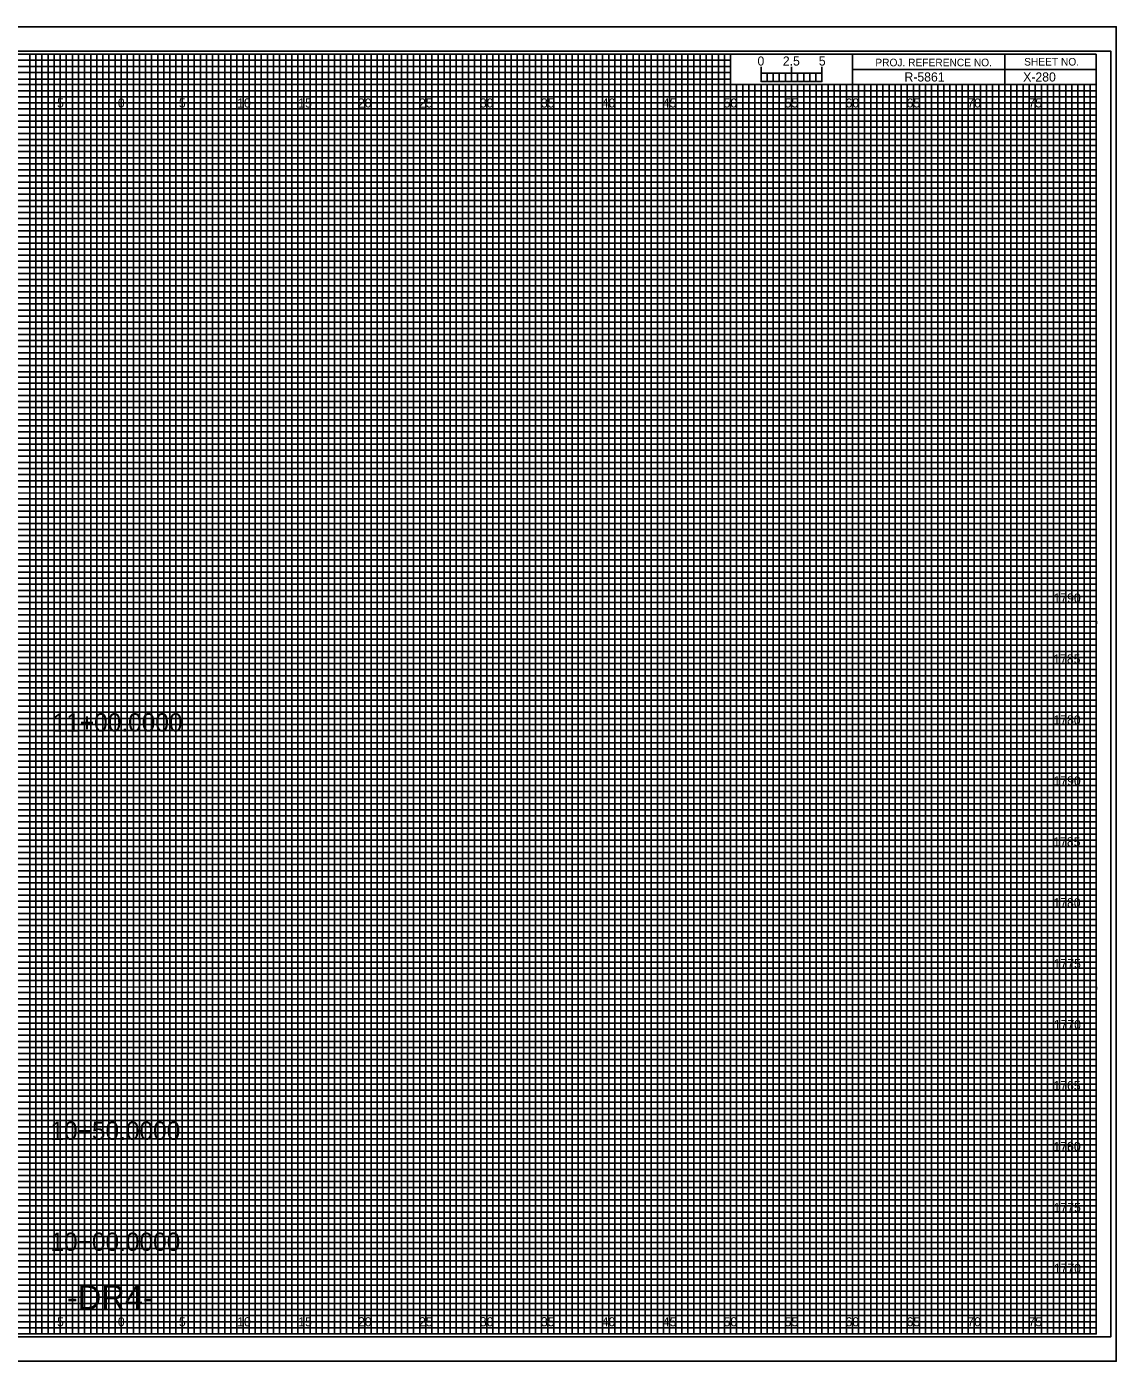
# Model space of a CAD drawing. Extents: x -7 to 162, y -2 to 107.
# Drawn here: x 72.2 to 161.7, y -2.3 to 107.3 of the extents above; entities that cross this region are included whole.
import ezdxf

# ---------------------------------------------------------------- set-up
doc = ezdxf.new("R2010")
doc.units = 0
for name, color, linetype in [('Prop XS Alignment Label', 7, 'Continuous'), ('Prop XS Bar Scale Labels', 7, 'Continuous'), ('Prop XS Elevation Labels', 7, 'Continuous'), ('Prop XS Offset Labels', 7, 'Continuous'), ('Prop XS Project Number', 7, 'Continuous'), ('Prop XS Sheet Number', 7, 'Continuous'), ('Prop XS Station Labels', 7, 'Continuous'), ('Sheet Cross Section CELL', 7, 'Continuous'), ('Sheet Cross Section Grid Major CELL', 7, 'Continuous'), ('Sheet Cross Section Grid Middle CELL', 7, 'Continuous'), ('Sheet Cross Section Grid Minor 1 CELL', 7, 'Continuous'), ('Sheet Cross Section Grid Minor 2 CELL', 7, 'Continuous'), ('Sheet Cross Section Scale CELL', 7, 'Continuous'), ('Sheet Cutting Line CELL', 7, 'Continuous'), ('Sheet DOT Grid CELL', 7, 'Continuous'), ('Sheet Plot Border Inside CELL', 7, 'Continuous'), ('Sheet Plot Border Outside CELL', 7, 'Continuous')]:
    doc.layers.add(name, color=color, linetype=linetype)

msp = doc.modelspace()

# ---------------------------------------------------------------- linework, layer by layer
at = {"layer": 'Sheet Cross Section CELL'}
for p, q in [((152.5, 105), (152.5, 102.5)), ((152.5, 102.5), (152.5, 105)), ((160, 103.75), (140, 103.75)), ((140, 103.75), (140, 102.5)), ((140, 102.5), (160, 102.5))]:
    msp.add_line(p, q, dxfattribs=at)
for points in [[(160, 105), (0, 105), (0, 0), (160, 0)], [(140, 105), (130, 105), (130, 102.52), (140, 102.52)], [(160, 105), (140, 105), (140, 102.5), (160, 102.5)]]:
    msp.add_lwpolyline(points, close=True, dxfattribs=at)
at = {"layer": 'Sheet Cross Section Grid Major CELL'}
for p, q in [((75, 105), (70, 105)), ((75, 0), (75, 105)), ((85, 105), (80, 105)), ((80, 105), (80, 0)), ((85, 0), (85, 105)), ((95, 105), (90, 105)), ((90, 105), (90, 0)), ((95, 0), (95, 105)), ((105, 105), (100, 105)), ((100, 105), (100, 0)), ((105, 0), (105, 105)), ((115, 105), (110, 105)), ((110, 105), (110, 0)), ((115, 0), (115, 105)), ((125, 105), (120, 105)), ((120, 105), (120, 0)), ((125, 0), (125, 105)), ((130, 105), (130, 0)), ((135, 0), (135, 102.5)), ((145, 102.5), (140, 102.5)), ((140, 102.5), (140, 0)), ((145, 0), (145, 102.5)), ((155, 102.5), (150, 102.5)), ((150, 102.5), (150, 0)), ((155, 0), (155, 102.5)), ((80, 0), (75, 0)), ((90, 0), (85, 0)), ((100, 0), (95, 0)), ((110, 0), (105, 0)), ((120, 0), (115, 0)), ((130, 0), (125, 0)), ((140, 0), (135, 0)), ((150, 0), (145, 0)), ((160, 0), (155, 0)), ((160, 0), (160, 0))]:
    msp.add_line(p, q, dxfattribs=at)
for points in [[(0, 100), (160, 100), (160, 95), (0, 95)], [(0, 90), (160, 90), (160, 85), (0, 85)], [(0, 80), (160, 80), (160, 75), (0, 75)], [(0, 70), (160, 70), (160, 65), (0, 65)], [(0, 60), (160, 60), (160, 55), (0, 55)], [(0, 50), (160, 50), (160, 45), (0, 45)], [(0, 40), (160, 40), (160, 35), (0, 35)], [(0, 30), (160, 30), (160, 25), (0, 25)], [(0, 20), (160, 20), (160, 15), (0, 15)], [(0, 10), (160, 10), (160, 5), (0, 5)]]:
    msp.add_lwpolyline(points, dxfattribs=at)
at = {"layer": 'Sheet Cross Section Grid Middle CELL'}
for points in [[(67.5, 105), (72.5, 105), (72.5, 0), (77.5, 0), (77.5, 105), (82.5, 105), (82.5, 0), (87.5, 0), (87.5, 105), (92.5, 105), (92.5, 0), (97.5, 0), (97.5, 105), (102.5, 105), (102.5, 0), (107.5, 0), (107.5, 105), (112.5, 105), (112.5, 0), (117.5, 0), (117.5, 105), (122.5, 105), (122.5, 0), (127.5, 0), (127.5, 105), (129.97, 105), (130, 105), (130, 102.5), (132.5, 102.5), (132.5, 0), (137.5, 0), (137.5, 102.5), (142.5, 102.5), (142.5, 0), (147.5, 0), (147.5, 102.5), (152.5, 102.5), (152.5, 0), (157.5, 0), (157.5, 102.5)], [(0, 102.5), (137.5, 102.5)], [(0, 92.5), (160, 92.5), (160, 97.5), (0, 97.5)], [(0, 82.5), (160, 82.5), (160, 87.5), (0, 87.5)], [(0, 72.5), (160, 72.5), (160, 77.5), (0, 77.5)], [(0, 62.5), (160, 62.5), (160, 67.5), (0, 67.5)], [(0, 52.5), (160, 52.5), (160, 57.5), (0, 57.5)], [(0, 42.5), (160, 42.5), (160, 47.5), (0, 47.5)], [(0, 32.5), (160, 32.5), (160, 37.5), (0, 37.5)], [(0, 22.5), (160, 22.5), (160, 27.5), (0, 27.5)], [(0, 12.5), (160, 12.5), (160, 17.5), (0, 17.5)], [(0, 2.5), (160, 2.5), (160, 7.5), (0, 7.5)]]:
    msp.add_lwpolyline(points, dxfattribs=at)
at = {"layer": 'Sheet Cross Section Grid Minor 1 CELL'}
for p, q in [((0, 104.5), (130, 104.5)), ((130, 104.5), (130, 103.99)), ((130, 103.99), (0, 103.99)), ((0, 103.5), (130, 103.5)), ((130, 102.95), (0, 102.95)), ((130, 103.5), (130, 102.95)), ((0, 102), (160, 102))]:
    msp.add_line(p, q, dxfattribs=at)
for points in [[(0, 101.5), (135, 101.5), (160, 101.5), (160, 101), (0, 101)], [(0, 100.5), (160, 100.5), (160, 99.5), (0, 99.5)], [(0, 99), (160, 99), (160, 98.5), (0, 98.49)], [(0, 98), (160, 98), (160, 97), (0, 97)], [(0, 96.5), (160, 96.5), (160, 96), (0, 96)], [(0, 95.5), (160, 95.5), (160, 94.5), (0, 94.5)], [(0, 94), (160, 94), (160, 93.5), (0, 93.5)], [(0, 93), (160, 93), (160, 92), (0, 92)], [(0, 91.5), (160, 91.5), (160, 91), (0, 91)], [(0, 90.5), (160, 90.5), (160, 89.5), (0, 89.5)], [(0, 89), (160, 89), (160, 88.5), (0, 88.5)], [(0, 88), (160, 88), (160, 86.98), (160, 86.5), (160, 86), (0, 86)], [(0, 87), (160, 87), (160, 86.5), (0, 86.5)], [(0, 85.5), (160, 85.5), (160, 84.5), (0, 84.52)], [(0, 84.52), (160, 84.5), (160, 84), (0, 84)], [(0, 83.5), (160, 83.5), (160, 83), (0, 83)], [(0, 82), (160, 82), (160, 81.5), (0, 81.5)], [(0, 81), (160, 81), (160, 80.5), (0, 80.5)], [(-0.04, 79.45), (160, 79.45), (160, 78.94), (-0.04, 78.94)], [(0, 78.5), (160, 78.5), (160, 78), (0, 78)], [(0, 77), (160, 77), (160, 76.5), (0, 76.5)], [(0, 76), (160, 76), (160, 75.5), (0, 75.5)], [(0, 74.5), (160, 74.5), (160, 74), (0, 74)], [(0, 73.5), (160, 73.5), (160, 73), (0, 73)], [(0, 72), (160, 72), (160, 71.5), (0, 71.5)], [(0, 71), (160, 71), (160, 70.5), (0, 70.5)], [(0, 69.5), (160, 69.5), (160, 68.99), (0, 69)], [(0, 68.5), (160, 68.5), (160, 68), (0, 68)], [(0, 67), (160, 67), (160, 66.5), (0, 66.5)], [(0, 66), (160, 66), (160, 65.5), (0, 65.5)], [(0, 64.5), (160, 64.5), (160, 64), (0, 64)], [(0, 63.5), (160, 63.5), (160, 63), (0, 63)], [(0, 62), (160, 62), (160, 61.5), (0, 61.5)], [(0, 61), (160, 61), (160, 60.5), (0, 60.5)], [(0, 59.5), (160, 59.5), (160, 59), (0, 59)], [(0, 58.5), (160.03, 58.45), (160, 58), (0, 58)], [(0, 57), (160, 57), (160, 56.5), (0, 56.5)], [(0, 56), (160, 56), (160, 55.5), (0, 55.5)], [(0, 54.5), (160, 54.5), (160, 54), (0, 54)], [(0, 53.5), (160, 53.5), (160, 53), (0, 53)], [(0, 52), (160, 52), (160, 51.5), (0, 51.5)], [(0, 51), (160, 51), (160, 50.5), (0, 50.5)], [(0, 49.5), (160, 49.5), (160, 49), (0, 49)], [(0, 48.5), (160, 48.5), (160, 48), (0, 48)], [(0, 47), (160, 47), (160, 46.5), (0, 46.5)], [(0, 46), (160, 46), (160, 45.5), (0, 45.5)], [(0, 44.5), (160, 44.5), (160, 44), (0, 44)], [(0, 43.5), (160, 43.5), (160, 43), (0, 43)], [(0, 42), (160, 42), (160, 41.5), (0, 41.5)], [(0, 41), (160, 41), (160, 40.5), (0, 40.5)], [(0, 39.5), (160, 39.5), (160, 38.99), (0, 39)], [(0, 38.5), (160, 38.5), (160, 38), (0, 38)], [(0, 37), (160, 37), (160, 36.5), (0, 36.5)], [(0, 36), (160, 36), (160, 35.5), (0, 35.5)], [(0, 34.5), (160, 34.5), (160, 34), (0, 34)], [(0, 33.5), (160, 33.5), (160, 33), (0, 33)], [(0, 32), (160, 32), (160, 31.5), (0, 31.5)], [(0, 31), (160, 31), (160, 30.5), (0, 30.5)], [(0, 29.5), (160, 29.5), (160, 29), (0, 29)], [(0, 28.5), (160.03, 28.46), (160, 28), (0, 28)], [(0, 27), (160, 27), (160, 26.5), (0, 26.5)], [(0, 26), (160, 26), (160, 25.5), (0, 25.5)], [(0, 24.5), (160, 24.5), (160, 24), (0, 24)], [(0, 23.5), (160, 23.5), (160, 23), (0, 23)], [(0, 22), (160, 22), (160, 21.5), (0, 21.5)], [(0, 21), (160, 21), (160, 20.5), (0, 20.5)], [(0, 19.5), (160, 19.5), (160, 19), (0, 19)], [(0, 18.5), (160, 18.5), (160, 18), (0, 18)], [(0, 17), (160, 17), (160, 16.5), (0, 16.5)], [(0, 16), (160, 16), (160, 15.5), (0, 15.5)], [(0, 14.5), (160, 14.5), (160, 14), (0, 14)], [(0, 13.5), (160, 13.5), (160, 13), (0, 13)], [(0, 12), (160, 12), (160, 11.5), (0, 11.5)], [(0, 11), (160, 11), (160, 10.5), (0, 10.5)], [(0, 9.5), (160, 9.5), (160, 9), (0, 9)], [(0, 8.5), (160, 8.5), (160, 8), (0, 8)], [(0, 7), (160, 7), (160, 6.5), (0, 6.5)], [(0, 6), (160, 6), (160, 5.5), (0, 5.5)], [(0, 4.5), (160, 4.5), (160, 4), (0, 4)], [(0, 3.5), (160, 3.5), (160, 3), (0, 3)], [(0, 2), (160, 2), (160, 1.5), (0, 1.5)], [(0, 1), (160, 1), (160, 0.5), (0, 0.5)]]:
    msp.add_lwpolyline(points, dxfattribs=at)
at = {"layer": 'Sheet Cross Section Grid Minor 2 CELL'}
for p, q in [((133.5, 102.5), (133, 102.5)), ((133, 102.5), (133, 0)), ((133.5, 0), (133.5, 102.5)), ((134.5, 102.5), (134, 102.5)), ((134, 102.5), (134, 0)), ((134.5, 0), (134.5, 102.5)), ((133, 0), (132.5, 0)), ((134, 0), (133.5, 0))]:
    msp.add_line(p, q, dxfattribs=at)
for points in [[(72.5, 0), (73, 0), (73, 105), (73.5, 105), (73.5, 0)], [(73.5, 0), (74, 0), (74, 105), (74.5, 105), (74.5, 0)], [(75, 0), (75.5, 0), (75.5, 105), (76, 105), (76, 0)], [(76, 0), (76.5, 0), (76.5, 105), (77, 105), (77, 0)], [(77.5, 0), (78, 0), (78, 105), (78.5, 105), (78.5, 0)], [(78.5, 0), (79, 0), (79, 105), (79.5, 105), (79.5, 0)], [(80, 0), (80.5, 0), (80.5, 105), (81, 105), (81, 0)], [(81, 0), (81.5, 0), (81.5, 105), (82, 105), (82, 0)], [(82.5, 0), (83, 0), (83, 105), (83.5, 105), (83.5, 0)], [(83.5, 0), (84, 0), (84, 105), (84.5, 105), (84.5, 0)], [(85, 0), (85.5, 0), (85.5, 105), (86, 105), (86, 0)], [(86, 0), (86.5, 0), (86.5, 105), (87, 105), (87, 0)], [(87.5, 0), (88, 0), (88, 105), (88.5, 105), (88.5, 0)], [(88.5, 0), (89, 0), (89, 105), (89.5, 105), (89.5, 0)], [(90, 0), (90.5, 0), (90.5, 105), (91, 105), (91, 0)], [(91, 0), (91.5, 0), (91.5, 105), (92, 105), (92, 0)], [(92.5, 0), (93, 0), (93, 105), (93.5, 105), (93.5, 0)], [(93.5, 0), (94, 0), (94, 105), (94.5, 105), (94.5, 0)], [(95, 0), (95.5, 0), (95.5, 105), (96, 105), (96, 0)], [(96, 0), (96.5, 0), (96.5, 105), (97, 105), (97, 0)], [(97.5, 0), (98, 0), (98, 105), (98.5, 105), (98.5, 0)], [(98.5, 0), (99, 0), (99, 105), (99.5, 105), (99.5, 0)], [(100, 0), (100.5, 0), (100.5, 105), (101, 105), (101, 0)], [(101, 0), (101.5, 0), (101.5, 105), (102, 105), (102, 0)], [(102.5, 0), (103, 0), (103, 105), (103.5, 105), (103.5, 0)], [(103.5, 0), (104, 0), (104, 105), (104.5, 105), (104.5, 0)], [(105, 0), (105.5, 0), (105.5, 105), (106, 105), (106, 0)], [(106, 0), (106.5, 0), (106.5, 105), (107, 105), (107, 0)], [(107.5, 0), (108, 0), (108, 105), (108.5, 105), (108.5, 0)], [(108.5, 0), (109, 0), (109, 105), (109.5, 105), (109.5, 0)], [(110, 0), (110.5, 0), (110.5, 105), (111, 105), (111, 0)], [(111, 0), (111.5, 0), (111.5, 105), (112, 105), (112, 0)], [(112.5, 0), (113, 0), (113, 105), (113.5, 105), (113.5, 0)], [(113.5, 0), (114, 0), (114, 105), (114.5, 105), (114.5, 0)], [(115, 0), (115.5, 0), (115.5, 105), (116, 105), (116, 0)], [(116, 0), (116.5, 0), (116.5, 105), (117, 105), (117, 0)], [(117.5, 0), (118, 0), (118, 105), (118.5, 105), (118.5, 0)], [(118.5, 0), (119, 0), (119, 105), (119.5, 105), (119.5, 0)], [(120, 0), (120.5, 0), (120.5, 105), (121, 105), (121, 0)], [(121, 0), (121.5, 0), (121.5, 105), (122, 105), (122, 0)], [(122.5, 0), (123, 0), (123, 105), (123.5, 105), (123.5, 0)], [(123.5, 0), (124, 0), (124, 105), (124.5, 105), (124.5, 0)], [(125, 0), (125.5, 0), (125.5, 105), (126, 105), (126, 0)], [(126, 0), (126.5, 0), (126.5, 105), (127, 105), (127, 0)], [(127.5, 0), (128, 0), (128, 105), (128.5, 105), (128.5, 0)], [(128.5, 0), (129, 0), (129, 105), (129.5, 105), (129.5, 0)], [(130, 0), (130.5, 0), (130.5, 102.5), (131.01, 102.5), (131.01, 0)], [(131, 0), (131.5, 0), (131.5, 102.5), (132, 102.5), (132, 0)], [(135, 0), (135.49, 0), (135.49, 102.5), (136, 102.5), (136, 0)], [(136, 0), (136.5, 0), (136.5, 102.5), (137.03, 102.5), (137.03, 0)], [(137.5, 0), (138, 0), (138, 102.5), (138.5, 102.5), (138.5, 0)], [(138.5, 0), (139, 0), (139, 102.5), (139.5, 102.5), (139.5, 0)], [(140, 0), (140.5, 0), (140.5, 102.5), (141, 102.5), (141, 0)], [(141, 0), (141.5, 0), (141.5, 102.5), (142, 102.5), (142, 0)], [(142.5, 0), (143, 0), (143, 102.5), (143.5, 102.5), (143.5, 0)], [(143.5, 0), (144, 0), (144, 102.5), (144.5, 102.5), (144.5, 0)], [(145, 0), (145.5, 0), (145.5, 102.5), (146, 102.5), (146, 0)], [(146, 0), (146.5, 0), (146.5, 102.5), (147, 102.5), (147, 0)], [(147.5, 0), (148, 0), (148, 102.5), (148.5, 102.5), (148.5, 0)], [(148.5, 0), (149, 0), (149, 102.5), (149.5, 102.5), (149.5, 0)], [(150, 0), (150.5, 0), (150.5, 102.5), (151, 102.5), (151, 0)], [(151, 0), (151.5, 0), (151.5, 102.5), (152, 102.5), (152, 0)], [(152.5, 0), (153, 0), (153, 102.5), (153.5, 102.5), (153.5, 0)], [(153.5, 0), (154, 0), (154, 102.5), (154.5, 102.5), (154.5, 0)], [(155, 0), (155.5, 0), (155.5, 102.5), (156, 102.5), (156, 0)], [(156, 0), (156.5, 0), (156.5, 102.5), (157, 102.5), (157, 0)], [(157.5, 0), (158, 0), (158, 102.5), (158.5, 102.5), (158.5, 0)], [(158.5, 0), (159, 0), (159, 102.5), (159.5, 102.5), (159.5, 0)]]:
    msp.add_lwpolyline(points, dxfattribs=at)
at = {"layer": 'Sheet Cross Section Scale CELL'}
for p, q in [((132.5, 102.75), (132.5, 103.95)), ((132.5, 103.45), (132.5, 103.95)), ((135, 102.75), (135, 103.95)), ((137.5, 102.75), (137.5, 103.95)), ((137.5, 103.45), (137.5, 103.95))]:
    msp.add_line(p, q, dxfattribs=at)
for points in [[(137.5, 103.45), (132.5, 103.45), (132.5, 102.75), (137.5, 102.75)], [(132.5, 103.45), (133, 103.45), (133, 102.75), (132.5, 102.75)], [(133.5, 103.45), (134, 103.45), (134, 102.75), (133.5, 102.75)], [(134.5, 103.45), (135, 103.45), (135, 102.75), (134.5, 102.75)], [(135.5, 103.45), (136, 103.45), (136, 102.75), (135.5, 102.75)], [(136.5, 103.45), (137, 103.45), (137, 102.75), (136.5, 102.75)]]:
    msp.add_lwpolyline(points, close=True, dxfattribs=at)
at = {"layer": 'Sheet Cutting Line CELL'}
for p, q in [((161.65, 107.25), (-6.7, 107.25)), ((-6.7, -2.25), (161.65, -2.25))]:
    msp.add_line(p, q, dxfattribs=at)
at = {"layer": 'Sheet DOT Grid CELL'}
for p, q in [((75, 0), (75, 105)), ((80, 0), (80, 105)), ((85, 0), (85, 105)), ((90, 0), (90, 105)), ((95, 0), (95, 105)), ((100, 0), (100, 105)), ((105, 0), (105, 105)), ((110, 0), (110, 105)), ((115, 0), (115, 105)), ((120, 0), (120, 105)), ((125, 0), (125, 105)), ((130, 0), (130, 102.34)), ((135, 0), (135, 102.34)), ((140, 0), (140, 102.34)), ((145, 0), (145, 102.34)), ((150, 0), (150, 102.34)), ((155, 0), (155, 102.34)), ((0, 100), (160, 100)), ((0, 95), (160, 95)), ((0, 90), (160, 90)), ((0, 85), (160, 85)), ((0, 80), (160, 80)), ((0, 75), (160, 75)), ((0, 70), (160, 70)), ((0, 65), (160, 65)), ((0, 60), (160, 60)), ((0, 55), (160, 55)), ((0, 50), (160, 50)), ((0, 45), (160, 45)), ((0, 40), (160, 40)), ((0, 35), (160, 35)), ((0, 30), (160, 30)), ((0, 25), (160, 25)), ((0, 20), (160, 20)), ((0, 15), (160, 15)), ((0, 10), (160, 10)), ((0, 5), (160, 5))]:
    msp.add_line(p, q, dxfattribs=at)
at = {"layer": 'Sheet Plot Border Inside CELL'}
msp.add_lwpolyline([(-5.4, -0.25), (161.2, -0.25), (161.2, 105.25), (-5.4, 105.25)], close=True, dxfattribs=at)
at = {"layer": 'Sheet Plot Border Outside CELL'}
msp.add_lwpolyline([(-6.7, -2.25), (161.65, -2.25), (161.65, 107.25), (-6.7, 107.25)], close=True, dxfattribs=at)

# ---------------------------------------------------------------- texts
at = {"layer": 'Prop XS Alignment Label'}
msp.add_text('-DR4-', height=2, dxfattribs=at).set_placement((75.55, 2))
at = {"layer": 'Prop XS Bar Scale Labels'}
for s, p in [('2.5', (134.29, 104.06)), ('5', (137.24, 104.06))]:
    msp.add_text(s, height=0.75, dxfattribs=at).set_placement(p)
at = {"layer": 'Prop XS Elevation Labels'}
for s, p in [('1790', (156.5, 60)), ('1785', (156.48, 55)), ('1780', (156.49, 50)), ('1790', (156.5, 45)), ('1785', (156.48, 40)), ('1780', (156.49, 35)), ('1775', (156.51, 30)), ('1770', (156.52, 25)), ('1765', (156.49, 20)), ('1780', (156.49, 15)), ('1760', (156.5, 15)), ('1775', (156.51, 10)), ('1770', (156.52, 5))]:
    msp.add_text(s, height=0.75, dxfattribs=at).set_placement(p)
at = {"layer": 'Prop XS Offset Labels'}
for s, p in [('5', (74.74, 100.62)), ('0', (79.73, 100.62)), ('0', (79.73, 100.62)), ('5', (84.74, 100.62)), ('10', (89.52, 100.62)), ('15', (94.53, 100.62)), ('20', (99.43, 100.62)), ('25', (104.44, 100.62)), ('30', (109.43, 100.62)), ('35', (114.44, 100.62)), ('40', (119.43, 100.62)), ('45', (124.44, 100.62)), ('50', (129.43, 100.62)), ('55', (134.44, 100.62)), ('60', (139.43, 100.62)), ('65', (144.44, 100.62)), ('70', (149.43, 100.62)), ('75', (154.44, 100.62)), ('5', (74.74, 0.62)), ('0', (79.73, 0.62)), ('0', (79.73, 0.62)), ('5', (84.74, 0.62)), ('10', (89.52, 0.62)), ('15', (94.53, 0.62)), ('20', (99.43, 0.62)), ('25', (104.44, 0.62)), ('30', (109.43, 0.62)), ('35', (114.44, 0.62)), ('40', (119.43, 0.62)), ('45', (124.44, 0.62)), ('50', (129.43, 0.62)), ('55', (134.44, 0.62)), ('60', (139.43, 0.62)), ('65', (144.44, 0.62)), ('70', (149.43, 0.62)), ('75', (154.44, 0.62))]:
    msp.add_text(s, height=0.75, dxfattribs=at).set_placement(p)
at = {"layer": 'Prop XS Project Number'}
msp.add_text('R-5861', height=0.75, dxfattribs=at).set_placement((144.27, 102.75))
at = {"layer": 'Prop XS Sheet Number'}
msp.add_text('X-280', height=0.75, dxfattribs=at).set_placement((154.01, 102.75))
at = {"layer": 'Prop XS Station Labels'}
for s, p in [('11+00.0000', (74.38, 49.42)), ('10+50.0000', (74.2, 15.92)), ('10+00.0000', (74.2, 6.81))]:
    msp.add_text(s, height=1.5, dxfattribs=at).set_placement(p)
at = {"layer": 'Sheet Cross Section CELL'}
for s, p in [('PROJ. REFERENCE NO.', (141.88, 104)), ('SHEET NO.', (154.09, 104.06))]:
    msp.add_text(s, height=0.625, dxfattribs=at).set_placement(p)
at = {"layer": 'Sheet Cross Section Scale CELL'}
msp.add_text('0', height=0.75, dxfattribs=at).set_placement((132.21, 104.06))

doc.saveas('drawing.dxf')
